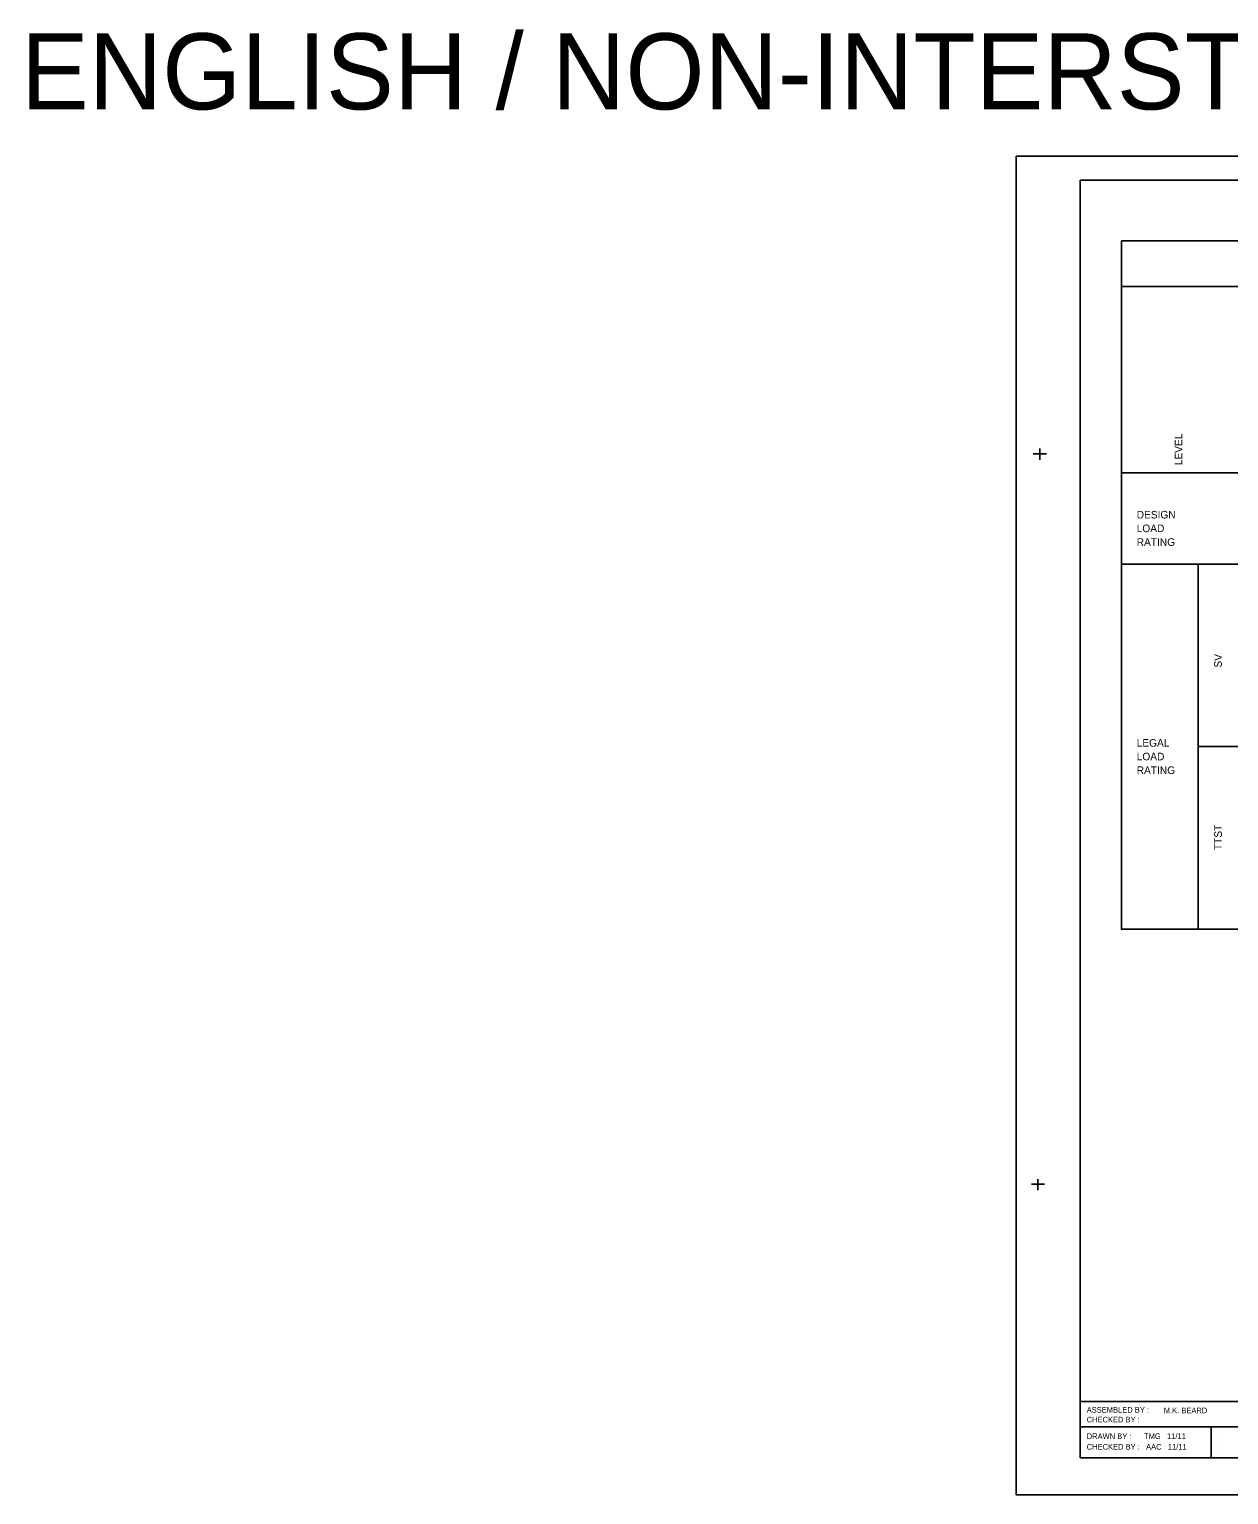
# Model space of a CAD drawing. Extents: x -169 to 381, y 285 to 620.
# Drawn here: x -169 to 28.2, y 284.7 to 525.5 of the extents above; entities that cross this region are included whole.
import ezdxf

# ---------------------------------------------------------------- set-up
doc = ezdxf.new("R2010")
doc.units = 0
for name, color, linetype in [('Bill of Material Border Lines', 7, 'Continuous'), ('Bill of Material Lines', 7, 'Continuous'), ('Plan Sheet', 7, 'Continuous'), ('Plan Sheet CELL', 7, 'Continuous'), ('Plot Shape CELL', 7, 'Continuous'), ('Text', 7, 'Continuous'), ('User Information Notes', 7, 'Continuous'), ('User Information Notes CELL', 7, 'Continuous')]:
    doc.layers.add(name, color=color, linetype=linetype)

msp = doc.modelspace()

# ---------------------------------------------------------------- linework, layer by layer
at = {"layer": 'Bill of Material Border Lines'}
msp.add_lwpolyline([(10.55, 490.71), (247.05, 490.71), (247.05, 377.59), (10.55, 377.59), (10.55, 490.71)], dxfattribs=at)
at = {"layer": 'Bill of Material Lines'}
for p, q in [((10.55, 483.21), (247.05, 483.21)), ((10.55, 452.59), (247.05, 452.59)), ((10.55, 437.59), (247.05, 437.59)), ((23.17, 437.59), (23.17, 377.59)), ((23.17, 407.59), (247.05, 407.59))]:
    msp.add_line(p, q, dxfattribs=at)
at = {"layer": 'Plan Sheet'}
for p, q in [((3.77, 299.98), (45.41, 299.98)), ((45.41, 295.8), (3.77, 295.8)), ((25.32, 290.71), (25.32, 295.8))]:
    msp.add_line(p, q, dxfattribs=at)
at = {"layer": 'Plan Sheet CELL'}
for p, q in [((-6.77, 504.65), (-6.77, 504.65)), ((3.77, 500.71), (323.78, 500.71)), ((3.77, 290.71), (3.77, 500.71)), ((-3.96, 455.71), (-1.76, 455.71)), ((-2.89, 454.71), (-2.89, 456.61)), ((-4.22, 335.71), (-2.12, 335.71)), ((-3.19, 334.72), (-3.19, 336.53)), ((3.77, 290.71), (323.78, 290.71)), ((-6.77, 284.65), (-6.77, 284.65))]:
    msp.add_line(p, q, dxfattribs=at)
at = {"layer": 'Plot Shape CELL'}
msp.add_lwpolyline([(-6.77, 504.65), (323.86, 504.65), (323.86, 284.65), (-6.77, 284.65)], close=True, dxfattribs=at)
at = {"layer": 'User Information Notes'}
for p, q in [((26.23, 294.9), (26.23, 294.9)), ((26.23, 293.34), (26.23, 293.34)), ((26.23, 291.79), (26.23, 291.79))]:
    msp.add_line(p, q, dxfattribs=at)
at = {"layer": 'User Information Notes CELL'}
for p, q in [((-6.77, 505.03), (-6.77, 505.03)), ((3.77, 500.71), (3.77, 500.71))]:
    msp.add_line(p, q, dxfattribs=at)

# ---------------------------------------------------------------- texts
at = {"layer": 'Plan Sheet'}
for s, height, p in [('ASSEMBLED BY :', 0.9255, (4.83, 298.13)), ('CHECKED BY :', 0.9255, (4.83, 296.53)), ('DRAWN BY :      TMG   11/11', 0.9258, (4.83, 293.8)), ('CHECKED BY :   AAC   11/11  ', 0.9258, (4.83, 292.06))]:
    msp.add_text(s, height=height, dxfattribs=at).set_placement(p)
at = {"layer": 'Text'}
for s, p in [('LEVEL', (20.55, 453.84)), ('SV', (27.05, 420.59)), ('TTST', (27.05, 390.59))]:
    msp.add_text(s, height=1.25, rotation=90, dxfattribs=at).set_placement(p)
for s, height, p in [('DESIGN', 1.25, (13.05, 445.09)), ('LOAD', 1.25, (13.05, 442.84)), ('RATING', 1.25, (13.05, 440.59)), ('LEGAL', 1.25, (13.05, 407.59)), ('LOAD', 1.25, (13.05, 405.34)), ('RATING', 1.25, (13.05, 403.09)), ('M.K. BEARD', 0.925, (17.51, 298.04))]:
    msp.add_text(s, height=height, dxfattribs=at).set_placement(p)
at = {"layer": 'User Information Notes'}
msp.add_text('ENGLISH / NON-INTERSTATE / PRESTRESSED CONCRETE GIRDERS ', height=12.5, dxfattribs=at).set_placement((-170.4, 512.32))

doc.saveas('drawing.dxf')
